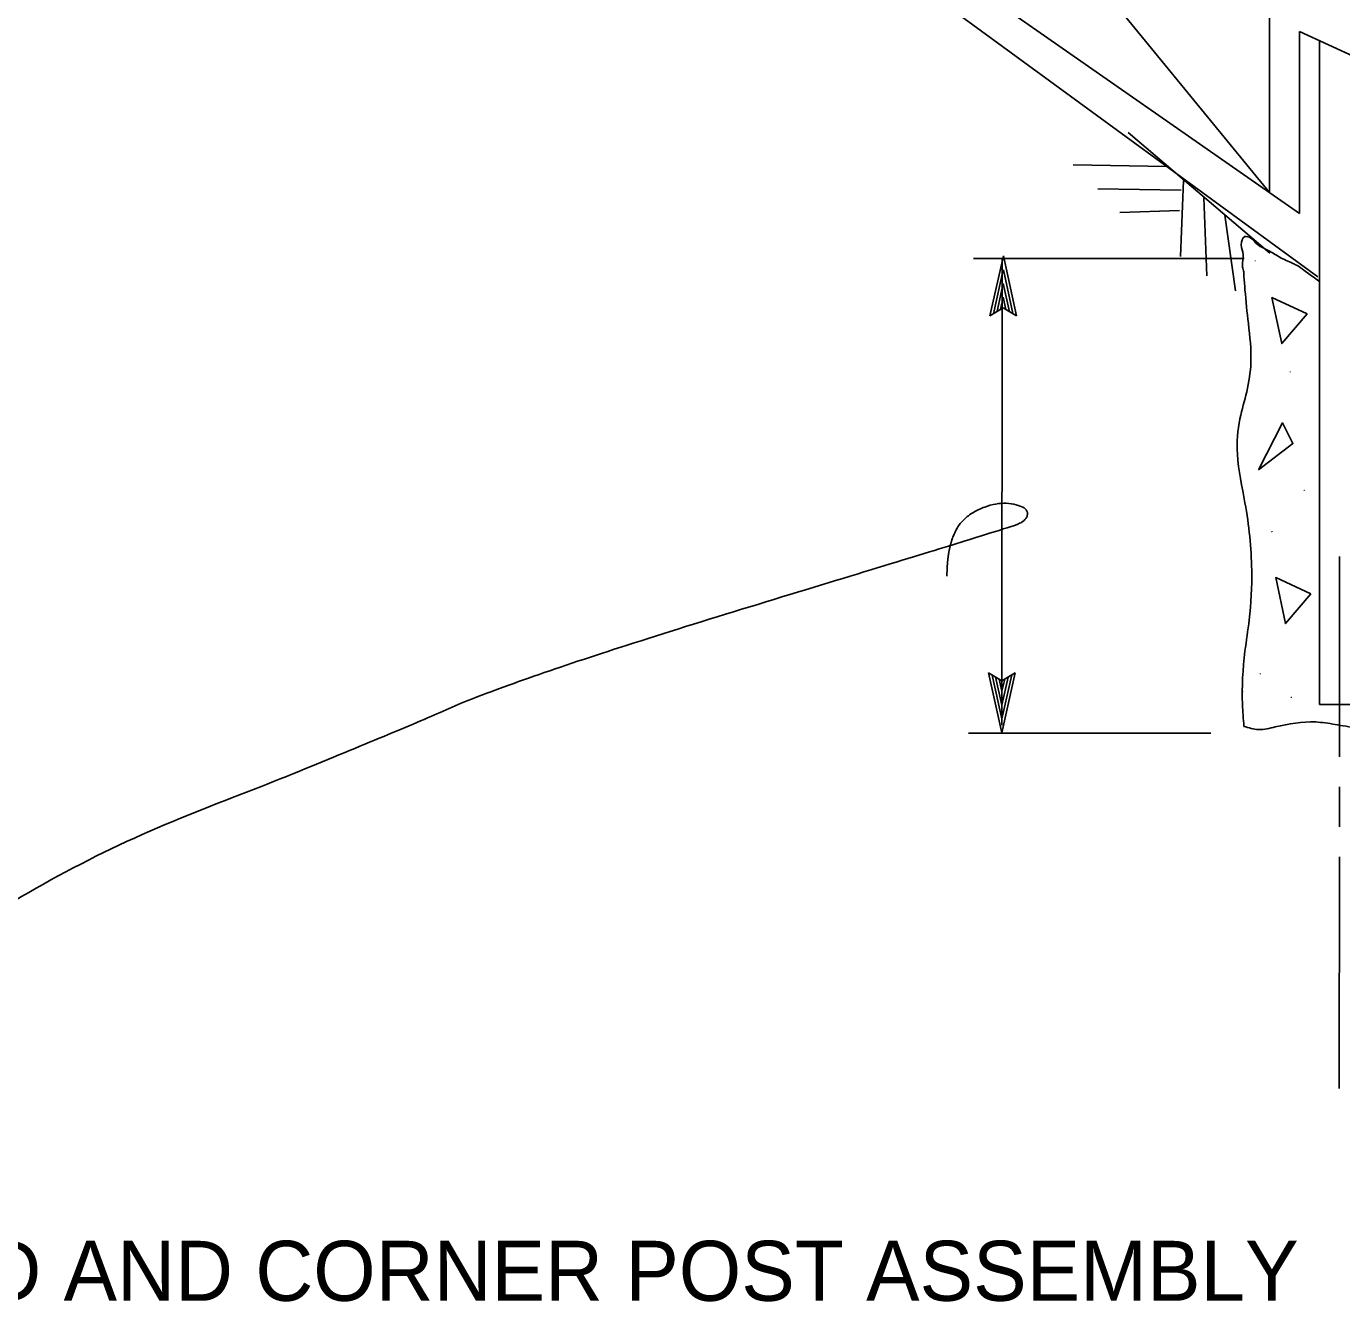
# Model space of a CAD drawing. Extents: x 6710407 to 6714861, y 1868090 to 1871317.
# Drawn here: x 6711572 to 6711703.6, y 1870248.9 to 1870376.3 of the extents above; entities that cross this region are included whole.
import ezdxf

# ---------------------------------------------------------------- set-up
doc = ezdxf.new("R2010")
doc.units = 0
for name, color, linetype in [('G-MARK', 7, 'Continuous'), ('G-TEXT', 7, 'Continuous'), ('Nongeo Data(60)', 7, 'Continuous')]:
    doc.layers.add(name, color=color, linetype=linetype)

msp = doc.modelspace()

# ---------------------------------------------------------------- linework, layer by layer
at = {"layer": 'G-MARK'}
for p, q in [((6711666.76, 1870353.13), (6711693.81, 1870353.13)), ((6711669.57, 1870306.47), (6711669.62, 1870353.16)), ((6711666.24, 1870305.68), (6711690.47, 1870305.68))]:
    msp.add_line(p, q, dxfattribs=at)
for points in [[(6711703.35, 1870323.33), (6711703.33, 1870303.33)], [(6711703.34, 1870300.33), (6711703.34, 1870296.33)], [(6711703.33, 1870293.33), (6711703.31, 1870270.16)]]:
    msp.add_lwpolyline(points, dxfattribs=at)
msp.add_open_spline([(6711552.02, 1870252.12), (6711532.44, 1870254.85), (6711565.91, 1870288.54), (6711607.21, 1870305), (6711621.64, 1870311.39), (6711669.92, 1870326.1), (6711672.14, 1870326.93), (6711672.14, 1870328.32), (6711669.08, 1870328.87), (6711665.48, 1870327.21), (6711664.09, 1870323.88), (6711664.09, 1870321.38)], degree=2, dxfattribs=at)
at = {"layer": 'G-TEXT'}
for p, q in [((6711668.38, 1870347.4), (6711669.73, 1870353.39)), ((6711669.73, 1870353.39), (6711669.73, 1870353.39)), ((6711669.73, 1870353.39), (6711671.05, 1870347.39)), ((6711668.74, 1870347.61), (6711669.72, 1870352.01)), ((6711669.73, 1870352), (6711670.69, 1870347.63)), ((6711669.1, 1870347.85), (6711669.72, 1870350.63)), ((6711669.72, 1870350.63), (6711670.35, 1870347.81)), ((6711669.72, 1870348.19), (6711668.38, 1870347.4)), ((6711669.44, 1870348.02), (6711669.72, 1870349.25)), ((6711669.72, 1870349.25), (6711669.99, 1870348.04)), ((6711671.05, 1870347.39), (6711669.72, 1870348.19)), ((6711668.38, 1870347.4), (6711668.38, 1870347.4)), ((6711671.05, 1870347.39), (6711671.05, 1870347.39)), ((6711669.57, 1870305.72), (6711668.25, 1870311.72)), ((6711668.25, 1870311.72), (6711668.25, 1870311.72)), ((6711668.25, 1870311.72), (6711669.58, 1870310.92)), ((6711669.57, 1870307.11), (6711668.61, 1870311.49)), ((6711669.58, 1870308.48), (6711668.95, 1870311.31)), ((6711670.92, 1870311.72), (6711669.57, 1870305.72)), ((6711670.56, 1870311.5), (6711669.57, 1870307.1)), ((6711669.58, 1870310.92), (6711670.92, 1870311.72)), ((6711670.92, 1870311.72), (6711670.92, 1870311.72)), ((6711669.58, 1870309.87), (6711669.31, 1870311.07)), ((6711670.2, 1870311.27), (6711669.58, 1870308.48)), ((6711669.86, 1870311.09), (6711669.58, 1870309.87)), ((6711669.57, 1870305.72), (6711669.57, 1870305.72))]:
    msp.add_line(p, q, dxfattribs=at)
at = {"layer": 'Nongeo Data(60)'}
for p, q in [((6711696.34, 1870359.71), (6711696.34, 1870458.63)), ((6711699.34, 1870357.62), (6711586.04, 1870436.57)), ((6711701.19, 1870351.28), (6711586.12, 1870435.32)), ((6711696.34, 1870359.71), (6711660.87, 1870403.05)), ((6711699.34, 1870357.62), (6711699.34, 1870375.83)), ((6711705.13, 1870373.15), (6711699.34, 1870375.83)), ((6711701.34, 1870361.2), (6711701.34, 1870374.83)), ((6711696.37, 1870353.67), (6711682.21, 1870365.71)), ((6711686.04, 1870362.33), (6711676.71, 1870362.49)), ((6711687.5, 1870359.95), (6711679.16, 1870360.08)), ((6711687.73, 1870360.93), (6711687.43, 1870353.33)), ((6711701.34, 1870308.53), (6711701.34, 1870361.2)), ((6711689.76, 1870359.2), (6711690.06, 1870351.39)), ((6711687.33, 1870357.93), (6711681.38, 1870357.73)), ((6711691.87, 1870357.46), (6711692.93, 1870349.9)), ((6711705.34, 1870308.53), (6711701.34, 1870308.53))]:
    msp.add_line(p, q, dxfattribs=at)
for points in [[(6711700.12, 1870347.58), (6711697.57, 1870344.62), (6711696.59, 1870349.22)], [(6711695.23, 1870332.01), (6711697.63, 1870336.69), (6711698.69, 1870334.63)], [(6711700.48, 1870319.6), (6711697.94, 1870316.64), (6711696.96, 1870321.24)]]:
    msp.add_lwpolyline(points, close=True, dxfattribs=at)
for points in [[(6711693.79, 1870351.36), (6711693.77, 1870351.78), (6711693.65, 1870352.27), (6711693.71, 1870353.51), (6711693.52, 1870354.5), (6711693.89, 1870355.31), (6711694.45, 1870355.18), (6711694.95, 1870354.69), (6711696.31, 1870353.88), (6711697.36, 1870353.26), (6711698.67, 1870352.64), (6711699.04, 1870352.46), (6711699.78, 1870351.96), (6711700.28, 1870351.59), (6711701.39, 1870350.78)], [(6711693.79, 1870351.36), (6711693.89, 1870349.99), (6711694.23, 1870346.63), (6711694.48, 1870342.75), (6711694.06, 1870339.81), (6711693.39, 1870337.11), (6711693.13, 1870333.58), (6711693.89, 1870328.69), (6711694.56, 1870321.96), (6711694.31, 1870316.99), (6711693.89, 1870313.87), (6711693.64, 1870308.57), (6711693.79, 1870306.36)], [(6711693.79, 1870306.36), (6711695.24, 1870306.04), (6711696.92, 1870306.3), (6711700.96, 1870306.8), (6711702.9, 1870306.55), (6711705.09, 1870306.21), (6711707.45, 1870306.04), (6711710.06, 1870305.96), (6711712.5, 1870306.04), (6711713.93, 1870306.21), (6711714.49, 1870306.36)]]:
    msp.add_spline(points, degree=3, dxfattribs=at)

# ---------------------------------------------------------------- texts
for p in [(6711694.84, 1870353.04), (6711698.34, 1870341.96), (6711699.74, 1870330.1), (6711696.52, 1870325.97), (6711695.37, 1870311.75), (6711693.61, 1870309.98), (6711698.46, 1870309.41)]:
    msp.add_text('.', height=0.8, rotation=271.1553, dxfattribs=at).set_placement(p)
msp.add_text('END AND CORNER POST ASSEMBLY', height=6, dxfattribs=at).set_placement((6711556.59, 1870248.94))

doc.saveas('drawing.dxf')
